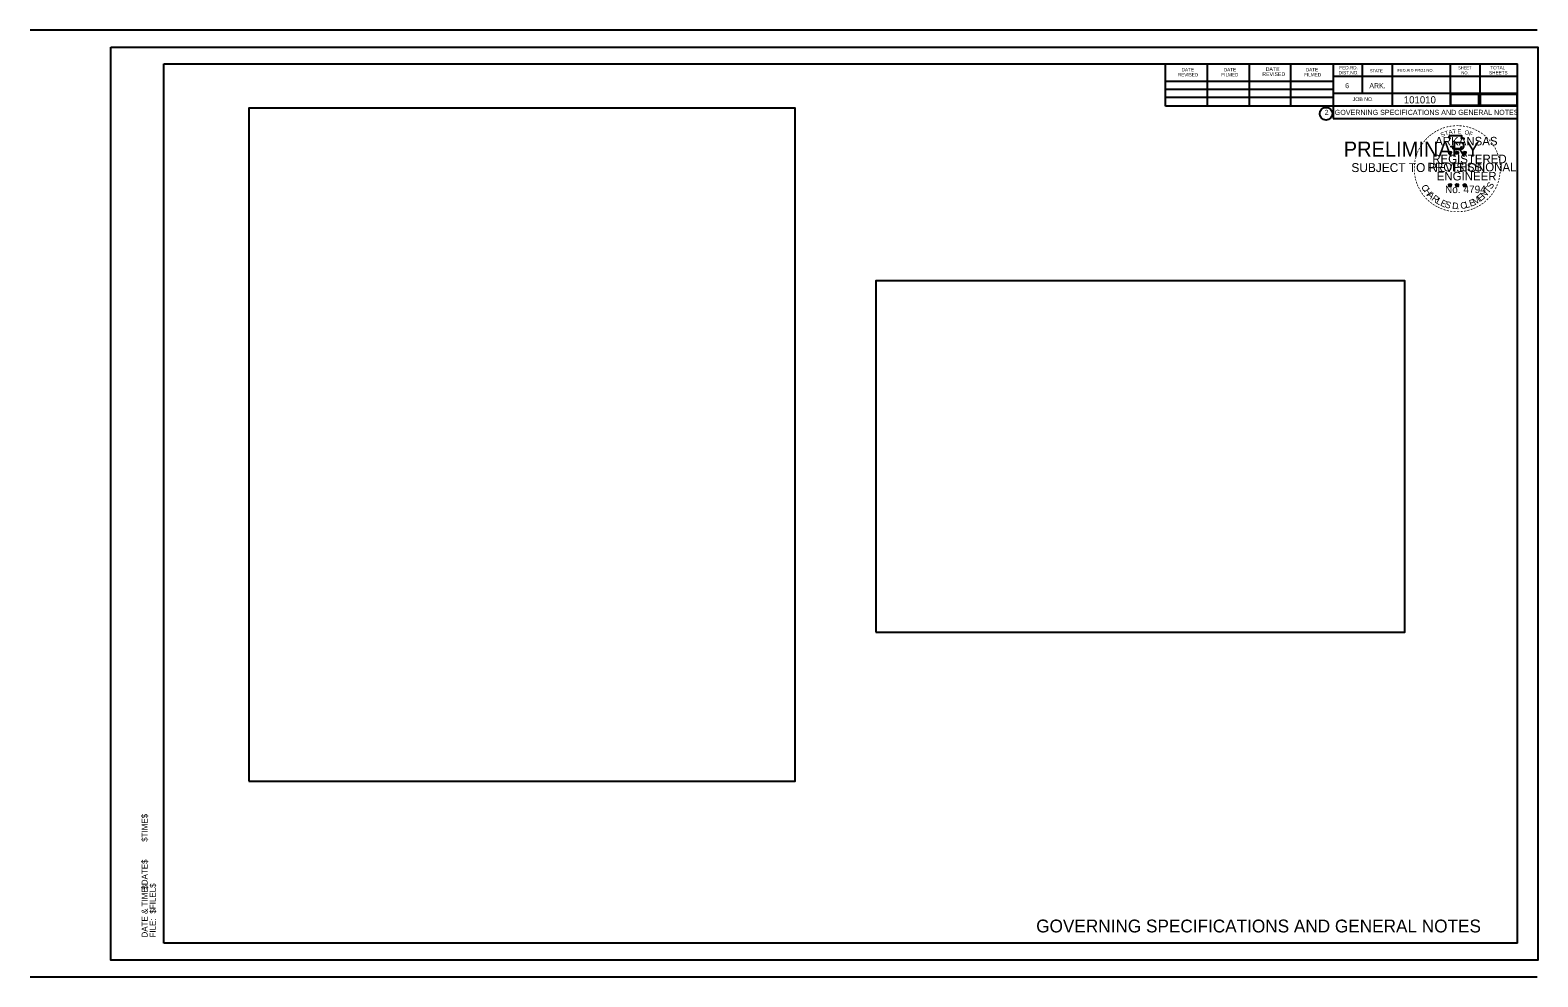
# Model space of a CAD drawing. Extents: x 3953 to 7490, y 10000 to 12548.
# Drawn here: x 5729 to 7490, y 10000 to 11106 of the extents above; entities that cross this region are included whole.
import ezdxf

# ---------------------------------------------------------------- set-up
doc = ezdxf.new("R2010")
doc.units = 0
for name, color, linetype in [('Default', 7, 'Continuous'), ('R_NoPlot', 7, 'Continuous'), ('STAMP_PE_FOSTER-SIGNATURE', 7, 'Continuous'), ('STAMP_PE_SEAL-INFO', 7, 'Continuous'), ('STAMP_PE_TAEGTMEYER', 7, 'Continuous'), ('STAMP_PRELIMINARY', 7, 'Continuous'), ('Total_Pages', 7, 'Continuous')]:
    doc.layers.add(name, color=color, linetype=linetype)

msp = doc.modelspace()

# ---------------------------------------------------------------- linework, layer by layer
at = {"layer": 'Default'}
for points in [[(7387.4, 11018.4), (7420.7, 11018.4), (7420.7, 11030.9), (7387.4, 11030.9)], [(5984.2, 10228.8), (6622.2, 10228.8), (6622.2, 11014.8), (5984.2, 11014.8)], [(6716.5, 10402.7), (7334.2, 10402.7), (7334.2, 10813.1), (6716.5, 10813.1)]]:
    msp.add_lwpolyline(points, close=True, dxfattribs=at)
at = {"layer": 'R_NoPlot'}
msp.add_lwpolyline([(5822.8, 11086.2), (7489.5, 11086.2), (7489.5, 10019.5), (5822.8, 10019.5)], close=True, dxfattribs=at)
at = {"layer": 'STAMP_PE_FOSTER-SIGNATURE'}
for p, q in [((7385.2, 10963.4), (7386.9, 10962.9)), ((7385.2, 10963.4), (7386.4, 10963.2)), ((7385.2, 10963.4), (7386.3, 10962.8)), ((7385.8, 10961.4), (7386.9, 10962.9)), ((7385.8, 10961.4), (7386.5, 10962.6)), ((7385.8, 10961.4), (7386.9, 10962.5)), ((7386.9, 10964.7), (7386.7, 10963.5)), ((7386.9, 10962.9), (7386.9, 10964.7)), ((7386.9, 10964.7), (7387.2, 10963.5)), ((7388.6, 10963.4), (7386.9, 10962.9)), ((7388, 10961.4), (7386.9, 10962.9)), ((7388, 10961.4), (7386.9, 10962.5)), ((7388.6, 10963.4), (7387.2, 10963.2)), ((7388, 10961.4), (7387.3, 10962.9)), ((7388.6, 10963.4), (7387.6, 10962.9)), ((7393.5, 10963.4), (7395.3, 10962.9)), ((7393.5, 10963.4), (7394.8, 10963.2)), ((7393.5, 10963.4), (7394.7, 10962.8)), ((7394.2, 10961.4), (7395.3, 10962.9)), ((7394.2, 10961.4), (7394.8, 10962.6)), ((7394.2, 10961.4), (7395.2, 10962.5)), ((7395.3, 10964.7), (7395.1, 10963.5)), ((7396.3, 10961.4), (7395.2, 10962.5)), ((7395.3, 10962.9), (7395.3, 10964.7)), ((7395.3, 10964.7), (7395.5, 10963.5)), ((7397, 10963.4), (7395.3, 10962.9)), ((7396.3, 10961.4), (7395.3, 10962.9)), ((7397, 10963.4), (7395.6, 10963.2)), ((7396.3, 10961.4), (7395.6, 10962.9)), ((7397, 10963.4), (7396, 10962.9)), ((7402.3, 10963.4), (7404.1, 10962.8)), ((7402.3, 10963.4), (7403.6, 10963.2)), ((7402.3, 10963.4), (7403.5, 10962.8)), ((7403, 10961.3), (7404.1, 10962.8)), ((7403, 10961.3), (7403.6, 10962.6)), ((7403, 10961.3), (7404.1, 10962.4)), ((7404.1, 10964.7), (7403.9, 10963.4)), ((7404.1, 10962.8), (7404.1, 10964.7)), ((7404.1, 10964.7), (7404.3, 10963.4)), ((7405.8, 10963.4), (7404.1, 10962.8)), ((7405.1, 10961.3), (7404.1, 10962.8)), ((7405.1, 10961.3), (7404.1, 10962.4)), ((7405.8, 10963.4), (7404.4, 10963.1)), ((7405.1, 10961.3), (7404.5, 10962.8)), ((7405.8, 10963.4), (7404.8, 10962.9)), ((7385.1, 10925.6), (7386.9, 10925)), ((7385.1, 10925.6), (7386.4, 10925.4)), ((7385.1, 10925.6), (7386.3, 10925)), ((7385.8, 10923.5), (7386.9, 10925)), ((7385.8, 10923.5), (7386.4, 10924.8)), ((7385.8, 10923.5), (7386.9, 10924.6)), ((7386.9, 10926.8), (7386.7, 10925.6)), ((7386.9, 10925), (7386.9, 10926.8)), ((7386.9, 10926.8), (7387.1, 10925.6)), ((7388.6, 10925.6), (7386.9, 10925)), ((7388, 10923.5), (7386.9, 10925)), ((7388, 10923.5), (7386.9, 10924.6)), ((7388.6, 10925.6), (7387.2, 10925.3)), ((7388, 10923.5), (7387.3, 10925)), ((7388.6, 10925.6), (7387.6, 10925.1)), ((7393.5, 10925.6), (7395.2, 10925)), ((7393.5, 10925.6), (7394.8, 10925.4)), ((7393.5, 10925.6), (7394.7, 10925)), ((7394.2, 10923.5), (7395.2, 10925)), ((7394.2, 10923.5), (7394.8, 10924.8)), ((7394.2, 10923.5), (7395.2, 10924.6)), ((7395.2, 10926.8), (7395, 10925.6)), ((7395.2, 10925), (7395.2, 10926.8)), ((7395.2, 10926.8), (7395.5, 10925.6)), ((7397, 10925.6), (7395.2, 10925)), ((7396.3, 10923.5), (7395.2, 10925)), ((7396.3, 10923.5), (7395.2, 10924.6)), ((7397, 10925.6), (7395.5, 10925.3)), ((7396.3, 10923.5), (7395.6, 10925)), ((7397, 10925.6), (7395.9, 10925.1)), ((7402.3, 10925.5), (7404.1, 10925)), ((7402.3, 10925.5), (7403.6, 10925.3)), ((7402.3, 10925.5), (7403.5, 10924.9)), ((7403, 10923.5), (7404.1, 10925)), ((7403, 10923.5), (7403.6, 10924.7)), ((7403, 10923.5), (7404.1, 10924.6)), ((7404.1, 10926.8), (7403.9, 10925.5)), ((7404.1, 10925), (7404.1, 10926.8)), ((7404.1, 10926.8), (7404.3, 10925.5)), ((7405.8, 10925.5), (7404.1, 10925)), ((7405.1, 10923.5), (7404.1, 10925)), ((7405.1, 10923.5), (7404.1, 10924.6)), ((7405.8, 10925.5), (7404.4, 10925.3)), ((7405.1, 10923.5), (7404.4, 10924.9)), ((7405.8, 10925.5), (7404.8, 10925))]:
    msp.add_line(p, q, dxfattribs=at)
for points in [[(7385.4, 10982.8), (7386.7, 10978.7)], [(7402.9, 10978.2), (7403.6, 10979.6), (7400.2, 10979.5), (7400.9, 10982.8), (7385.4, 10982.8)], [(7387.8, 10970.7), (7387.8, 10970.3), (7390.6, 10970.2), (7390.4, 10967.8), (7399.7, 10967.8), (7400.7, 10970.5)], [(7386.9, 10964.7), (7388, 10961.4), (7385.2, 10963.4), (7388.6, 10963.4), (7385.8, 10961.4), (7386.9, 10964.7)], [(7395.3, 10964.7), (7396.3, 10961.4), (7393.5, 10963.4), (7397, 10963.4), (7394.2, 10961.4), (7395.3, 10964.7)], [(7404.1, 10964.7), (7405.1, 10961.3), (7402.3, 10963.4), (7405.8, 10963.4), (7403, 10961.3), (7404.1, 10964.7)], [(7386.9, 10926.8), (7388, 10923.5), (7385.1, 10925.6), (7388.6, 10925.6), (7385.8, 10923.5), (7386.9, 10926.8)], [(7395.2, 10926.8), (7396.3, 10923.5), (7393.5, 10925.6), (7397, 10925.6), (7394.2, 10923.5), (7395.2, 10926.8)], [(7404.1, 10926.8), (7405.1, 10923.5), (7402.3, 10925.5), (7405.8, 10925.5), (7403, 10923.5), (7404.1, 10926.8)]]:
    msp.add_lwpolyline(points, dxfattribs=at)
for centre, radius in [((7386.9, 10962.9), 0.861), ((7386.9, 10962.9), 0.723), ((7386.9, 10962.9), 0.579), ((7386.9, 10962.9), 0.495), ((7386.9, 10962.9), 0.374), ((7386.9, 10962.9), 0.248), ((7386.9, 10962.9), 0.148), ((7395.3, 10962.9), 0.861), ((7395.3, 10962.9), 0.723), ((7395.3, 10962.9), 0.579), ((7395.3, 10962.9), 0.495), ((7395.3, 10962.9), 0.374), ((7395.3, 10962.9), 0.248), ((7395.3, 10962.9), 0.148), ((7404.1, 10962.8), 0.861), ((7404.1, 10962.8), 0.723), ((7404.1, 10962.8), 0.579), ((7404.1, 10962.8), 0.495), ((7404.1, 10962.8), 0.374), ((7404.1, 10962.8), 0.248), ((7404.1, 10962.8), 0.148), ((7386.9, 10925), 0.861), ((7386.9, 10925), 0.723), ((7386.9, 10925), 0.579), ((7386.9, 10925), 0.495), ((7386.9, 10925), 0.374), ((7386.9, 10925), 0.248), ((7386.9, 10925), 0.148), ((7395.2, 10925), 0.861), ((7395.2, 10925), 0.723), ((7395.2, 10925), 0.579), ((7395.2, 10925), 0.495), ((7395.2, 10925), 0.374), ((7395.2, 10925), 0.248), ((7395.2, 10925), 0.148), ((7404.1, 10925), 0.861), ((7404.1, 10925), 0.723), ((7404.1, 10925), 0.579), ((7404.1, 10925), 0.495), ((7404.1, 10925), 0.374), ((7404.1, 10925), 0.248), ((7404.1, 10925), 0.148)]:
    msp.add_circle(centre, radius, dxfattribs=at)
at = {"layer": 'STAMP_PRELIMINARY'}
for p, q in [((7488.8, 11106.1), (5728.8, 11106.1)), ((5884.9, 11066.7), (7465.8, 11066.7)), ((5884.9, 10039.4), (5884.9, 11066.7)), ((6647.5, 11065.4), (6647.5, 11065.4)), ((6647.5, 11065.4), (6647.5, 11065.4)), ((7054.5, 11017.3), (7054.5, 11066.7)), ((7103.8, 11017.3), (7103.8, 11065.7)), ((7152.6, 11017.3), (7152.6, 11065.7)), ((7201, 11017.3), (7201, 11065.7)), ((7250.3, 11066.7), (7250.3, 11002.7)), ((7284.5, 11066.7), (7284.5, 11032)), ((7319.2, 11066.7), (7319.2, 11017.3)), ((7387.1, 11066.7), (7387.1, 11017.3)), ((7421.8, 11066.7), (7421.8, 11017.3)), ((7465.8, 10039.4), (7465.8, 11066.7)), ((7054.5, 11046.6), (7250.3, 11046.6)), ((7465.8, 11052), (7250.3, 11052)), ((7465.8, 11052.1), (7465.8, 11052.1)), ((7054.5, 11037.3), (7250.3, 11037.3)), ((7054.5, 11027.6), (7250.3, 11027.6)), ((7465.8, 11032), (7250.3, 11032)), ((7465.8, 11017.3), (7054.5, 11017.3)), ((7250.3, 11002.7), (7465.8, 11002.7)), ((7465.8, 10039.4), (5884.9, 10039.4)), ((5728.8, 10000), (7488.8, 10000))]:
    msp.add_line(p, q, dxfattribs=at)
msp.add_circle((7242.2, 11008.4), 7.33, dxfattribs=at)
at = {"layer": 'Total_Pages'}
msp.add_lwpolyline([(7422.2, 11018.4), (7465.3, 11018.4), (7465.3, 11030.9), (7422.2, 11030.9)], close=True, dxfattribs=at)

# ---------------------------------------------------------------- texts
at = {"layer": 'Default'}
for s, height, p in [('$TIME$', 6.98, (5865.9, 10157.8)), ('$DATE$', 6.98, (5865.9, 10101.9)), ('$FILEL$', 6.98, (5875.5, 10073.9)), ('DATE & TIME:', 6.984, (5865.9, 10046)), ('FILE: ', 6.98, (5875.5, 10046))]:
    msp.add_text(s, height=height, rotation=90, dxfattribs=at).set_placement(p)
at = {"layer": 'STAMP_PE_FOSTER-SIGNATURE'}
for s, height, rotation, p in [('-', 8, 34.0636, (7369.8, 10983.7)), ('-', 8, 28.7918, (7372.8, 10985.5)), ('-', 8, 24.3072, (7375.9, 10987.1)), ('-', 8, 19.1761, (7379.1, 10988.5)), ('T', 5, 16.4036, (7381.7, 10982.9)), ('-', 8, 13.6302, (7382.9, 10989.7)), ('A', 5, 11.2132, (7385.8, 10984.1)), ('-', 8, 10.2193, (7386.2, 10990.5)), ('T', 5, 6.0228, (7390.1, 10985)), ('-', 8, 5.8968, (7389.9, 10991)), ('-', 8, 0.1862, (7393.8, 10991.4)), ('E', 5, 0.8323, (7395.6, 10985.5)), ('-', 8, 357.743, (7397.4, 10991.3)), ('-', 8, 352.1617, (7401.1, 10991)), ('O', 5, 350.4515, (7403.6, 10984.5)), ('-', 8, 347.2049, (7404.7, 10990.5)), ('F', 5, 340.0707, (7408.4, 10983.3)), ('-', 8, 342.3362, (7407.9, 10989.7)), ('-', 8, 337.8551, (7411.5, 10988.6)), ('-', 8, 334.1211, (7414.7, 10987.2)), ('-', 8, 329.6409, (7417.6, 10985.8)), ('-', 8, 58.0706, (7354.4, 10967.4)), ('-', 8, 54.2325, (7356, 10970.1)), ('-', 8, 50.6142, (7358.1, 10972.9)), ('-', 8, 48.4231, (7360.1, 10975.3)), ('-', 8, 42.9622, (7362.4, 10977.7)), ('-', 8, 38.9507, (7364.5, 10979.8)), ('-', 8, 36.2317, (7366.9, 10981.7)), ('S', 5, 21.594, (7377.1, 10981.2)), ('-', 8, 325.8627, (7420.8, 10984)), ('-', 8, 320.5297, (7423.8, 10981.9)), ('-', 8, 315.5786, (7426.8, 10979.4)), ('-', 8, 309.8797, (7429.7, 10976.7)), ('-', 8, 306.6522, (7432.3, 10973.7)), ('-', 7, 303.6753, (7434.7, 10970.8)), ('-', 8, 81.2013, (7348.8, 10951)), ('-', 8, 75.461, (7349.5, 10954.6)), ('-', 8, 72.3945, (7350.5, 10958.2)), ('-', 8, 67.7743, (7351.5, 10961.3)), ('-', 8, 62.8713, (7352.8, 10964.4)), ('-', 8, 299.6684, (7436.3, 10967.8)), ('-', 8, 294.6628, (7438, 10964.7)), ('-', 8, 290.5728, (7439.2, 10961.9)), ('-', 8, 285.1233, (7440.4, 10959)), ('-', 8, 280.5493, (7441.4, 10955.3)), ('-', 8, 94.1959, (7348.5, 10940.5)), ('-', 8, 89.0622, (7348.3, 10944.1)), ('-', 8, 85.1863, (7348.4, 10947.6)), ('-', 8, 98.9479, (7348.8, 10937.1)), ('-', 8, 101.7149, (7349.5, 10933.5)), ('-', 8, 260.9953, (7442.2, 10938)), ('-', 8, 276.5962, (7442.2, 10951.4)), ('-', 8, 263.5172, (7442.6, 10941.3)), ('-', 8, 274.3301, (7442.5, 10947.8)), ('-', 8, 269.9407, (7442.7, 10944.6)), ('-', 8, 105.4578, (7350.3, 10930.5)), ('-', 8, 109.0874, (7351.4, 10927.3)), ('-', 8, 114.0643, (7352.7, 10924.3)), ('-', 8, 115.7289, (7354.2, 10921.3)), ('-', 8, 120.4471, (7356, 10918.3)), ('C', 7.7, 296.9133, (7353, 10923.3)), ('H', 7.7, 303.2799, (7356, 10918.1)), ('N', 7.7, 45.1449, (7426.9, 10909.3)), ('T', 7.7, 51.5114, (7431.7, 10914.5)), ('S', 7.7, 57.878, (7435.3, 10919.7)), ('-', 8, 239.0712, (7436.4, 10920.8)), ('-', 8, 244.6197, (7438.4, 10924.5)), ('-', 8, 247.8887, (7439.7, 10927.7)), ('-', 8, 255.7626, (7440.7, 10931.2)), ('-', 8, 255.7626, (7441.7, 10934.7)), ('-', 8, 125.8934, (7358, 10915.5)), ('-', 8, 130.7181, (7360.3, 10912.8)), ('-', 8, 134.2238, (7362.9, 10910)), ('A', 7.7, 316.013, (7359.6, 10913)), ('-', 8, 138.9338, (7365.5, 10907.7)), ('-', 8, 144.6463, (7368.3, 10905.7)), ('R', 7.7, 322.3796, (7364.8, 10908.1)), ('-', 8, 148.0898, (7371.1, 10903.8)), ('-', 8, 151.5704, (7374, 10902.2)), ('L', 7.7, 328.7461, (7369.9, 10904.3)), ('-', 8, 154.6002, (7376.6, 10901)), ('E', 7.7, 335.1127, (7374.9, 10901.5)), ('S', 7.7, 341.4792, (7380.2, 10899.4)), ('D', 7.7, 354.2124, (7389.1, 10897.3)), ('C', 7.7, 6.9455, (7399.5, 10897.1)), ('L', 7.7, 13.3121, (7405.4, 10898.1)), ('E', 7.7, 19.6786, (7410.9, 10899.7)), ('M', 7.7, 32.4117, (7416.1, 10901.5)), ('-', 8, 207.3568, (7419, 10903.3)), ('E', 7.7, 38.7783, (7422.5, 10905.6)), ('-', 8, 212.2491, (7421.8, 10905)), ('-', 8, 215.7363, (7424.5, 10907)), ('-', 8, 221.0851, (7427.2, 10909.3)), ('-', 8, 225.7653, (7429.8, 10911.9)), ('-', 8, 231.2538, (7432.2, 10914.7)), ('-', 8, 233.8452, (7434.4, 10917.5)), ('-', 8, 158.5612, (7379.7, 10899.7)), ('-', 8, 162.7983, (7383.2, 10898.6)), ('-', 8, 167.5555, (7386.7, 10897.8)), ('-', 8, 173.1155, (7390.6, 10897.3)), ('-', 8, 176.5183, (7394.3, 10897)), ('-', 8, 181.5918, (7398.1, 10897.1)), ('.', 7.7, 0.5789, (7394.9, 10896.9)), ('-', 8, 185.8167, (7402.1, 10897.5)), ('-', 8, 191.2858, (7405.8, 10898.1)), ('-', 8, 195.4743, (7409.4, 10899.1)), ('-', 8, 200.7184, (7412.8, 10900.3)), ('-', 8, 204.2516, (7415.9, 10901.7))]:
    msp.add_text(s, height=height, rotation=rotation, dxfattribs=at).set_placement(p)
for s, height, p in [('ARKANSAS', 10, (7369.6, 10971.4)), ('REGISTERED', 10, (7366.2, 10950.6)), ('PROFESSIONAL', 10, (7360.5, 10941.1)), ('ENGINEER', 10, (7371.4, 10930.5)), ('No. 4794', 8.78, (7381.1, 10915.7))]:
    msp.add_text(s, height=height, dxfattribs=at).set_placement(p)
at = {"layer": 'STAMP_PE_SEAL-INFO'}
for s, height, p in [('PRELIMINARY', 17.5, (7262.8, 10958.4)), ('SUBJECT TO REVISION', 10.376, (7271.8, 10940.3))]:
    msp.add_text(s, height=height, dxfattribs=at).set_placement(p)
at = {"layer": 'STAMP_PE_TAEGTMEYER'}
for s, height, p in [('101010', 8.4, (7333, 11020.5)), ('GOVERNING SPECIFICATIONS AND GENERAL NOTES', 6, (7252.4, 11007))]:
    msp.add_text(s, height=height, dxfattribs=at).set_placement(p)
at = {"layer": 'STAMP_PRELIMINARY'}
for s, height, p in [('DATE', 3.91, (7073.5, 11057.9)), ('DATE', 3.91, (7122.8, 11057.9)), ('DATE', 4.4, (7171.7, 11058.4)), ('DATE', 3.91, (7218.6, 11057.9)), ('DIST.NO.', 3.91, (7256.7, 11054.4)), ('FED.RD.', 3.91, (7257.7, 11060.3)), ('STATE', 3.42, (7293.3, 11056.9)), ('FED.AID PROJ.NO.', 3.42, (7325.6, 11057.4)), ('SHEET', 3.42, (7396.4, 11060.3)), ('NO.', 3.42, (7400.3, 11054.4)), ('SHEETS', 3.91, (7432.6, 11054.4)), ('TOTAL', 3.91, (7434, 11060.3)), ('REVISED', 3.91, (7069.1, 11052)), ('FILMED', 3.91, (7119.9, 11052)), ('REVISED', 4.4, (7167.8, 11052.5)), ('FILMED', 3.91, (7216.6, 11052)), ('6', 5.86, (7264.5, 11038.3)), ('ARK.', 5.86, (7292.8, 11038.3)), ('JOB NO.', 4.4, (7273.3, 11023.2)), ('2', 5.86, (7240.6, 11007.1)), ('GOVERNING SPECIFICATIONS AND GENERAL NOTES', 15, (6903.7, 10051.9))]:
    msp.add_text(s, height=height, dxfattribs=at).set_placement(p)

doc.saveas('drawing.dxf')
